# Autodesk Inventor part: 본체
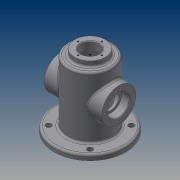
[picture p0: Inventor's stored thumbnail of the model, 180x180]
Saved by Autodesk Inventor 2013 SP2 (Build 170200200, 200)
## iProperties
Created: 2014-12
Part Number: 본체
Material: Generic
Document SubType Name: Modeling
Designer: user
Density: 1 g/cm^3
Author: user
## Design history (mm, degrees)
sketch "스케치1"
  geometry: C1 r 32.5 at (0, 0); 1 further point
  constraints: 1 centre point, 1 coincident
  dimensions: "d0" = 65 diameter of C1
extrude "돌출1" new body sketch "스케치1" distance "d1" = 90; taper "d2" = 0 deg
sketch "스케치2"
  geometry: C1 r 22.5 at (0, 0); 1 further point
  constraints: 1 centre point, 1 coincident
  dimensions: "d3" = 45 diameter of C1
extrude "돌출2" join sketch "스케치2" distance "d4" = 8; taper "d5" = 0 deg
node "작업 평면2"
  node "작업 평면1"
sketch "스케치3"
  geometry: L1 (-32.5, -90)-(32.5, -90) reference; C1 r 25 at (0, -43); 1 further point
  constraints: 1 centre point
  dimensions: "d7" = 50 diameter of C1; "d8" = 47 distance from line of C1.centre L1
extrude "돌출3" join sketch "스케치3" stored distance "d9" = 10; taper "d10" = 0 deg
sketch "스케치4"
  geometry: C1 r 25 at (0, 0) reference; C2 r 16 at (0, 0); 1 further point
  constraints: 1 centre point, 1 coincident
  dimensions: "d11" = 32 diameter of C2
extrude "돌출4" cut sketch "스케치4" distance "d12" = 12; taper "d13" = 0 deg
sketch "스케치5"
  geometry: L1 (-47, 32.5)-(-47, -32.5) reference; C1 r 12.5 at (0, 0); 1 further point
  constraints: 1 centre point
  dimensions: "d14" = 25 diameter of C1; "d15" = 47 distance from line of C1.centre L1
sketch "스케치6"
  geometry: C1 r 27.5 at (0, 0); 1 further point
  constraints: 1 centre point, 1 coincident
  dimensions: "d16" = 55 diameter of C1
extrude "돌출5" cut sketch "스케치6" distance "d17" = 85; taper "d18" = 0 deg
extrude "돌출6" cut sketch "스케치5" stored distance "d19" = 85; taper "d20" = 0 deg
sketch "스케치7"
  geometry: C1 r 52.5 at (0, 0); 1 further point
  constraints: 1 centre point, 1 coincident
  dimensions: "d21" = 105 diameter of C1
extrude "돌출7" join sketch "스케치7" distance "d22" = 8; taper "d23" = 0 deg
sketch "스케치8"
  geometry: C1 r 27.5 at (0, 0); 1 further point
  constraints: 1 centre point, 1 coincident
  dimensions: "d24" = 55 diameter of C1
extrude "돌출8" cut sketch "스케치8" distance "d26" = 8; taper "d27" = 0 deg
sketch "스케치9"
  geometry: C1 r 25 at (0, 0) reference; 5 further points
hole "구멍1" sketch "스케치9" at (20.5, 0), (0, -20.5), (-20.5, 0), (0, 20.5) diameter "d29" = 2.459; stored, may be unused: countersink angle "d33" = 90 deg, drill point angle "d35" = 118 deg; dims "d30" = 6, "d31" = 4, "d32" = 2, "d34" = 8
sketch "스케치10"
  geometry: C1 r 13.5 at (0, 0); 1 further point
  constraints: 1 centre point, 1 coincident
  dimensions: "d36" = 27 diameter of C1
extrude "돌출9" cut sketch "스케치10" stored distance "d37" = 8; taper "d38" = 0 deg
sketch "스케치11"
  geometry: 5 further points
hole "구멍2" sketch "스케치11" at (0, 17.5), (17.5, 0), (0, -17.5), (-17.5, 0) diameter "d40" = 2.459; stored, may be unused: countersink angle "d44" = 90 deg, drill point angle "d46" = 118 deg; dims "d41" = 6, "d42" = 4, "d43" = 2, "d45" = 8
node "작업 평면3"
sketch "스케치12"
  geometry: 2 further points
  constraints: 1 other
  dimensions: "d47" = 9 vertical distance of point (0, 0) point (1.017, -9)
feature "엠보싱1" sketch "스케치12" dims "d13" = 0, "d48" = 1, "d49" = 0
sketch "스케치13"
  geometry: L1 (0, 0)-(100, 0); C1 r 4 at (30.406, 30.406); 1 further point
  constraints: 2 end point, 1 centre point, 1 coincident, 1 horizontal
  dimensions: "d53" = 8 diameter of C1
extrude "돌출10" cut sketch "스케치13" distance "d54" = 8; taper "d55" = 0 deg
fillet "모깎기1" dims "d59" = 3
chamfer "모따기1" distance "d60" = 1; stored, may be unused: second distance "d61" = 2, angle "d62" = 45 deg
fillet "모깎기2" dims "d63" = 0.3
fillet "모깎기3" dims "d64" = 3
sketch "스케치14"
  geometry: 1 further point
node "솔리드1"
mirror "대칭1"
pattern_circular "원형 패턴1" dims angle "d57" = 360 deg
